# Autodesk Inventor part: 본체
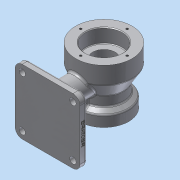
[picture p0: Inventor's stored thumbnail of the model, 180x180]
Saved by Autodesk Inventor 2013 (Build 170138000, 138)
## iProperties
Created: 2019-01
Part Number: 본체
Material: 알루미늄 6061
Document SubType Name: Modeling
Designer: Administrator
Density: 2.71 g/cm^3
Mass: 909.04 g
Surface Area: 594.743 cm^2
Volume: 335.439 cm^3
Author: Administrator
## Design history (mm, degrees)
sketch "스케치2"
  geometry: L1 (0, 40)-(0, -40); L2 (0, 40)-(40, 40); L3 (40, 40)-(40, 15); L4 (0, -40)-(35, -40); L5 (35, -40)-(35, -25); L6 (35, -25)-(28, -19.126); L7 (28, -5.785)-(40, 15); L8 (28, -5.785)-(28, -19.126); 2 further points
  constraints: 16 end point, 4 perpendicular, 1 coincident, 1 midpoint
  dimensions: "d6" = 80 distance of L1.start L1.end; "d7" = 40 distance of L1.start L2.end; "d8" = 25 distance of L2.end L3.end; "d9" = 35 distance of L1.end L4.end; "d10" = 15 distance of L4.end L5.end; "d14" = 20.78461 vertical distance of L7.start L3.end; "d15" = 13.34169 distance of L7.start L6.end; "d16" = 5.8737 vertical distance of L5.end L6.end; "d17" = 30 deg angle of L8 L7; "d18" = 130 deg angle of L6 L8
revolve "회전1" sketch "스케치2" stored, may be unused: angle "d19" = 90 deg
hole "구멍1" diameter "d22" = 52; stored, may be unused: countersink angle "d26" = 90 deg, drill point angle "d28" = 0 deg; dims "d20" = 10, "d21" = 10, "d23" = 6, "d24" = 4, "d25" = 2, "d27" = 20
hole "구멍2" diameter "d31" = 40; stored, may be unused: countersink angle "d35" = 90 deg, drill point angle "d37" = 0 deg; dims "d29" = 10, "d30" = 10, "d32" = 6, "d33" = 4, "d34" = 2, "d36" = 17
hole "구멍3" diameter "d40" = 32; stored, may be unused: countersink angle "d44" = 90 deg, drill point angle "d46" = 0 deg; dims "d38" = 10, "d39" = 10, "d41" = 6, "d42" = 4, "d43" = 2, "d45" = 17
chamfer "모따기1" distance "d47" = 1; stored, may be unused: second distance "d48" = 2, angle "d49" = 45 deg
sketch "스케치3"
  geometry: L1 (-40, 40)-(40, 40) reference; L2 (-80, 35)-(-80, -57); L3 (-80, -57)-(-70, -57); L4 (-80, 35)-(-70, 35); L5 (-70, 35)-(-70, -57); L6 (-28, -5.785)-(-28, -19.126) reference; 1 further point
  constraints: 8 end point, 2 perpendicular, 1 parallel
  dimensions: "d53" = 92 distance of L2.start L2.end; "d54" = 10 distance of L2.end L3.end; "d55" = 10 distance of L2.start L4.end; "d56" = 5 distance from line of L1 L4.end; "d57" = 42 distance from line of L3.end L6
extrude "돌출2" join sketch "스케치3" stored distance "d58" = 92; taper "d59" = 0 deg
fillet "모깎기2" dims "d60" = 10
sketch "스케치4"
  geometry: L1 (82, 82)-(82, 10) reference; L2 (31, 45.199)-(31, 82); L3 (41, 45.199)-(41, 82); L4 (31, 82)-(41, 82); A1 r 10 centre (72, 10) between (72, 0) and (82, 10) reference; A2 r 16 centre (36, 30) between (31, 45.199) and (41, 45.199); 1 further point
  constraints: 6 end point, 3 parallel, 2 point on circle, 1 centre point, 1 perpendicular
  dimensions: "d62" = 32 diameter of A2; "d67" = 36.80132 distance of L3.start L3.end; "d68" = 10 distance of L2.end L3.end; "d69" = 31 distance from line of A1.centre L3; "d70" = 35.19868 vertical distance of A1.centre L3.start
extrude "돌출3" join sketch "스케치4" stored distance "d71" = 92; taper "d72" = 0 deg
feature "면 기울기1" dims angle "d73" = 25 deg
sketch "스케치5" dims "d74" = 66
  geometry: C1 r 27 at (0, 0) reference; 2 further points
  constraints: 1 coincident, 1 vertical alignment, 2 other
hole "구멍4" sketch "스케치5" at (0, 33) diameter "d75" = 3.242; stored, may be unused: countersink angle "d79" = 90 deg, drill point angle "d81" = 118 deg; dims "d76" = 9, "d77" = 4, "d78" = 2, "d80" = 11
sketch "스케치6" dims "d85" = 55
  geometry: C1 r 21 at (0, 0) reference; 2 further points
  constraints: 1 coincident, 1 vertical alignment, 2 other
hole "구멍5" sketch "스케치6" at (0, 27.5) diameter "d86" = 3.242; stored, may be unused: countersink angle "d90" = 90 deg, drill point angle "d92" = 118 deg; dims "d87" = 9, "d88" = 4, "d89" = 2, "d91" = 11
fillet "모깎기3" dims "d96" = 1
fillet "모깎기4" dims "d97" = 0.6
fillet "모깎기5" dims "d98" = 3
fillet "모깎기8" dims "d101" = 3
fillet "모깎기9" dims "d102" = 3
node "작업 평면1"
sketch "스케치7"
  geometry: L1 (-80, 25)-(-80, -47) reference; L2 (-73, 35)-(-80, 35) reference; 2 further points
  constraints: 1 other
  dimensions: "d104" = 4 distance from line of point (-76, -11) L1; "d105" = 46 distance from line of L2 point (-76, -11)
feature "엠보싱1" sketch "스케치7" dims "d6" = 80, "d7" = 40, "d8" = 25, "d9" = 35, "d10" = 15, "d14" = 20.78461, "d15" = 13.34169, "d16" = 5.8737, "d17" = 30 deg, "d18" = 130 deg, "d41" = 6, "d106" = 0.5, "d107" = 0
sketch "스케치8"
  geometry: A1 r 7 centre (0, -7) between (0, 0) and (-7, -7) reference; 2 further points
  constraints: 1 coincident
hole "구멍6" sketch "스케치8" at (0, -7) diameter "d108" = 9; stored, may be unused: countersink angle "d112" = 90 deg, drill point angle "d114" = 118 deg; dims "d109" = 6, "d110" = 4, "d111" = 2, "d113" = 8
sketch "스케치9"
  geometry: A1 r 7 centre (72, -79) between (72, -86) and (79, -79) reference; 2 further points
  constraints: 1 coincident
hole "구멍7" sketch "스케치9" at (72, -79) diameter "d115" = 9; stored, may be unused: countersink angle "d119" = 90 deg, drill point angle "d121" = 118 deg; dims "d116" = 6, "d117" = 4, "d118" = 2, "d120" = 8
node "솔리드2"
pattern_circular "원형 패턴1" dims angle "d83" = 360 deg
pattern_circular "원형 패턴2" dims angle "d94" = 360 deg
mirror "대칭1"
mirror "대칭2"
